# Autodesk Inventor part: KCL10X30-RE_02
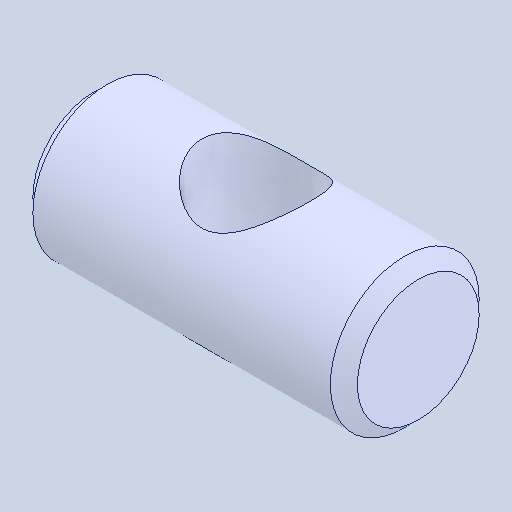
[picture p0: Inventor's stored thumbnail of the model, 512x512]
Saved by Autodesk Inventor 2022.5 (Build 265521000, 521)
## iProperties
Created: 2024-08
Part Number: KCL10X30-RE_02
Material: 一般
Document SubType Name: Modeling
Designer: ImaoCorp
Density: 1 g/cm^3
Appearance: 既定
Author: ImaoCorp
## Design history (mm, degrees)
feature "KCL10X30-RE_02"
node "ソリッド1"
